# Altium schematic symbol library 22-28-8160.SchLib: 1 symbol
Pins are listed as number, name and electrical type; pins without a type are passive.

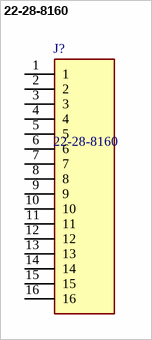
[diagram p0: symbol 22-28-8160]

## 22-28-8160
designator J?
Headers & Wire Housings BKWY HDR R/A 16P tin; Manufacturer_Name: Molex; Geometry.Height: 2mm
footprint 22288160
pins: 1, 2, 3, 4, 5, 6, 7, 8, 9, 10, 11, 12, 13, 14, 15, 16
